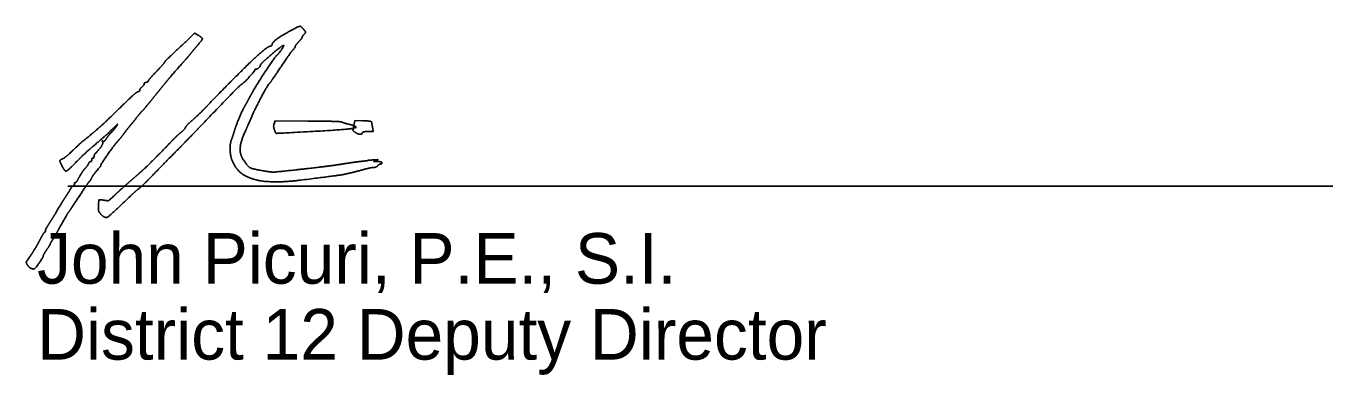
# Model space of a CAD drawing. Extents: x 0 to 34, y 0 to 22.
# Drawn here: x 25.965 to 29.58, y 2.758 to 3.723 of the extents above; entities that cross this region are included whole.
import ezdxf

# ---------------------------------------------------------------- set-up
doc = ezdxf.new("R2010")
doc.units = 0
doc.layers.add('SH_Data', color=7, linetype='Continuous')
doc.layers.add('SH_Text', color=7, linetype='Continuous')

msp = doc.modelspace()

# ---------------------------------------------------------------- linework, layer by layer
at = {"layer": 'SH_Data'}
msp.add_line((26.0803, 3.2806), (29.5803, 3.2806), dxfattribs=at)
at = {"layer": 'SH_Text'}
for p, q in [((26.6518, 3.4365), (26.6518, 3.4365)), ((26.8747, 3.4296), (26.8747, 3.4296)), ((26.1704, 3.204), (26.1704, 3.204)), ((25.9794, 3.0525), (25.9794, 3.0525))]:
    msp.add_line(p, q, dxfattribs=at)
for points in [[(26.4203, 3.693), (26.4311, 3.7036), (26.4407, 3.6979)], [(26.2143, 3.4456), (26.2176, 3.452), (26.2113, 3.4456)], [(26.7445, 3.4603), (26.6539, 3.4608), (26.6512, 3.4529)], [(26.8963, 3.4611), (26.8745, 3.4616), (26.8716, 3.4479)], [(26.91, 3.4312), (26.9248, 3.4312), (26.9231, 3.4442)]]:
    msp.add_lwpolyline(points, dxfattribs=at)
for points in [[(26.3787, 3.6538), (26.3956, 3.6695), (26.4143, 3.6871), (26.4203, 3.693)], [(26.4407, 3.6979), (26.4523, 3.6911), (26.4529, 3.685), (26.4431, 3.6743)], [(26.6456, 3.6725), (26.6456, 3.6777), (26.6716, 3.6968), (26.6977, 3.7108)], [(26.6977, 3.7108), (26.7203, 3.7229), (26.7254, 3.7229), (26.7351, 3.7113)], [(26.7288, 3.6923), (26.7288, 3.6911), (26.7245, 3.6854), (26.7192, 3.6798)], [(26.734, 3.7005), (26.7312, 3.6973), (26.7288, 3.6936), (26.7288, 3.6923)], [(26.7351, 3.7113), (26.7386, 3.7071), (26.7384, 3.7053), (26.734, 3.7005)], [(26.348, 3.6231), (26.348, 3.6242), (26.3618, 3.638), (26.3787, 3.6538)], [(26.4431, 3.6743), (26.4392, 3.67), (26.4302, 3.6592), (26.4231, 3.6505)], [(26.4663, 3.5026), (26.5366, 3.5762), (26.6286, 3.6644), (26.6374, 3.6666)], [(26.6776, 3.6693), (26.6776, 3.6716), (26.6526, 3.6522), (26.6291, 3.6318)], [(26.6374, 3.6666), (26.6419, 3.6677), (26.6456, 3.6704), (26.6456, 3.6725)], [(26.6602, 3.644), (26.6648, 3.648), (26.6776, 3.6667), (26.6776, 3.6693)], [(26.7056, 3.6599), (26.6975, 3.6508), (26.6943, 3.6464), (26.6679, 3.6072)], [(26.7096, 3.6669), (26.7096, 3.6655), (26.7078, 3.6623), (26.7056, 3.6599)], [(26.7192, 3.6798), (26.7139, 3.6742), (26.7096, 3.6684), (26.7096, 3.6669)], [(26.3256, 3.5976), (26.3379, 3.6105), (26.348, 3.622), (26.348, 3.6231)], [(26.4056, 3.6295), (26.3943, 3.6174), (26.3634, 3.582), (26.3527, 3.5688)], [(26.4231, 3.6505), (26.4161, 3.6418), (26.4082, 3.6323), (26.4056, 3.6295)], [(26.5863, 3.5314), (26.5982, 3.5538), (26.6536, 3.6382), (26.6602, 3.644)], [(26.6136, 3.6157), (26.6136, 3.6119), (26.605, 3.604), (26.601, 3.604)], [(26.6291, 3.6318), (26.6206, 3.6244), (26.6137, 3.6172), (26.6136, 3.6157)], [(26.3032, 3.5717), (26.3032, 3.573), (26.3133, 3.5847), (26.3256, 3.5976)], [(26.5975, 3.6016), (26.5974, 3.5987), (26.5643, 3.5624), (26.5618, 3.5624)], [(26.601, 3.604), (26.5991, 3.604), (26.5976, 3.6029), (26.5975, 3.6016)], [(26.6679, 3.6072), (26.6531, 3.5852), (26.6402, 3.5665), (26.6393, 3.5656)], [(26.2748, 3.5417), (26.2784, 3.5428), (26.2805, 3.5446), (26.2795, 3.5455)], [(26.2795, 3.5455), (26.2785, 3.5465), (26.2812, 3.5506), (26.2854, 3.5545)], [(26.2854, 3.5545), (26.2897, 3.5585), (26.2925, 3.5624), (26.2916, 3.5633)], [(26.2916, 3.5633), (26.2907, 3.5642), (26.2929, 3.5659), (26.2966, 3.5671)], [(26.2966, 3.5671), (26.3002, 3.5683), (26.3032, 3.5703), (26.3032, 3.5717)], [(26.3527, 3.5688), (26.3463, 3.5609), (26.3363, 3.5486), (26.3305, 3.5416)], [(26.5618, 3.5624), (26.5598, 3.5624), (26.5291, 3.5312), (26.4594, 3.4585)], [(26.6393, 3.5656), (26.6324, 3.5591), (26.5929, 3.4832), (26.58, 3.452)], [(26.1458, 3.4241), (26.1631, 3.4383), (26.1971, 3.4698), (26.2383, 3.5102)], [(26.2383, 3.5102), (26.2549, 3.5264), (26.2713, 3.5406), (26.2748, 3.5417)], [(26.3046, 3.5096), (26.2961, 3.499), (26.2875, 3.4889), (26.2855, 3.4872)], [(26.3305, 3.5416), (26.3248, 3.5345), (26.3131, 3.5201), (26.3046, 3.5096)], [(26.5717, 3.5048), (26.5734, 3.5074), (26.5799, 3.5194), (26.5863, 3.5314)], [(26.2855, 3.4872), (26.2835, 3.4854), (26.2762, 3.4768), (26.2693, 3.468)], [(26.4255, 3.4632), (26.4364, 3.4729), (26.4548, 3.4906), (26.4663, 3.5026)], [(26.5416, 3.4344), (26.5465, 3.4507), (26.565, 3.4938), (26.5717, 3.5048)], [(26.2113, 3.4456), (26.1995, 3.4336), (26.1769, 3.4132), (26.1528, 3.3928)], [(26.2016, 3.4296), (26.2067, 3.4349), (26.2124, 3.4421), (26.2143, 3.4456)], [(26.255, 3.4504), (26.2541, 3.4495), (26.2465, 3.4399), (26.2382, 3.429)], [(26.2693, 3.468), (26.2624, 3.4592), (26.256, 3.4513), (26.255, 3.4504)], [(26.4594, 3.4585), (26.4342, 3.4322), (26.3985, 3.3954), (26.38, 3.3767)], [(26.3939, 3.4295), (26.4003, 3.4348), (26.4056, 3.4406), (26.4056, 3.4424)], [(26.4056, 3.4424), (26.4056, 3.4442), (26.4146, 3.4536), (26.4255, 3.4632)], [(26.58, 3.452), (26.5771, 3.4449), (26.5734, 3.4363), (26.5718, 3.4328)], [(26.6512, 3.4529), (26.6497, 3.4483), (26.6499, 3.4414), (26.6518, 3.4365)], [(26.6518, 3.4365), (26.6557, 3.4263), (26.6587, 3.4262), (26.7512, 3.4312)], [(26.8388, 3.4575), (26.8368, 3.4588), (26.7944, 3.4601), (26.7445, 3.4603)], [(26.7512, 3.4312), (26.8528, 3.4366), (26.8897, 3.444), (26.8559, 3.452)], [(26.8559, 3.452), (26.8485, 3.4537), (26.8408, 3.4562), (26.8388, 3.4575)], [(26.8716, 3.4479), (26.8691, 3.4361), (26.8695, 3.4335), (26.8747, 3.4296)], [(26.9197, 3.4589), (26.9188, 3.4598), (26.9083, 3.4608), (26.8963, 3.4611)], [(26.9231, 3.4442), (26.9221, 3.4514), (26.9206, 3.458), (26.9197, 3.4589)], [(26.0927, 3.3776), (26.114, 3.3979), (26.1197, 3.4028), (26.1458, 3.4241)], [(26.1569, 3.3709), (26.1685, 3.3829), (26.1787, 3.3993), (26.1766, 3.4027)], [(26.2189, 3.405), (26.2122, 3.3982), (26.172, 3.3419), (26.172, 3.3392)], [(26.1766, 3.4027), (26.1752, 3.405), (26.1756, 3.4057), (26.1776, 3.4045)], [(26.1776, 3.4045), (26.1794, 3.4034), (26.1834, 3.4064), (26.1866, 3.4112)], [(26.1866, 3.4112), (26.1897, 3.416), (26.1964, 3.4243), (26.2016, 3.4296)], [(26.2382, 3.429), (26.2299, 3.4181), (26.2212, 3.4073), (26.2189, 3.405)], [(26.28, 3.3176), (26.2927, 3.3287), (26.3383, 3.3739), (26.3643, 3.4012)], [(26.3643, 3.4012), (26.3742, 3.4115), (26.3875, 3.4243), (26.3939, 3.4295)], [(26.5351, 3.3508), (26.5299, 3.3628), (26.5288, 3.3981), (26.5333, 3.4094)], [(26.5333, 3.4094), (26.535, 3.4135), (26.5387, 3.4247), (26.5416, 3.4344)], [(26.5718, 3.4328), (26.5589, 3.4053), (26.5557, 3.3692), (26.5648, 3.3551)], [(26.8747, 3.4296), (26.8817, 3.4243), (26.8952, 3.4232), (26.8952, 3.428)], [(26.8952, 3.428), (26.8952, 3.4297), (26.9019, 3.4312), (26.91, 3.4312)], [(26.0658, 3.3558), (26.069, 3.3568), (26.0811, 3.3666), (26.0927, 3.3776)], [(26.1528, 3.3928), (26.1396, 3.3816), (26.1207, 3.3642), (26.1109, 3.3543)], [(26.1528, 3.3621), (26.1528, 3.3647), (26.1546, 3.3686), (26.1569, 3.3709)], [(26.38, 3.3767), (26.3615, 3.358), (26.3331, 3.3289), (26.3168, 3.3121)], [(26.0649, 3.335), (26.0584, 3.3475), (26.0587, 3.3535), (26.0658, 3.3558)], [(26.1109, 3.3543), (26.0798, 3.3229), (26.0727, 3.3199), (26.0649, 3.335)], [(26.1122, 3.3058), (26.1168, 3.3142), (26.124, 3.3249), (26.1282, 3.3294)], [(26.1282, 3.3294), (26.1324, 3.334), (26.1367, 3.34), (26.1378, 3.3428)], [(26.1378, 3.3428), (26.1389, 3.3457), (26.1413, 3.348), (26.1431, 3.348)], [(26.1431, 3.348), (26.1449, 3.348), (26.1464, 3.3501), (26.1464, 3.3528)], [(26.1464, 3.3528), (26.1464, 3.3554), (26.1478, 3.3576), (26.1496, 3.3576)], [(26.1496, 3.3576), (26.1514, 3.3576), (26.1528, 3.3596), (26.1528, 3.3621)], [(26.172, 3.3392), (26.172, 3.3371), (26.1686, 3.3326), (26.1533, 3.3142)], [(26.5974, 3.2987), (26.5717, 3.3063), (26.5447, 3.3289), (26.5351, 3.3508)], [(26.5648, 3.3551), (26.5776, 3.3351), (26.5908, 3.3277), (26.6234, 3.3222)], [(26.7112, 3.3253), (26.7672, 3.3314), (26.8172, 3.3378), (26.8488, 3.3428)], [(26.8488, 3.3428), (26.8616, 3.3448), (26.8917, 3.3488), (26.9016, 3.3498)], [(26.9262, 3.3319), (26.9223, 3.3319), (26.9084, 3.3289), (26.8952, 3.3253)], [(26.9016, 3.3498), (26.906, 3.3503), (26.9096, 3.3509), (26.9096, 3.3512)], [(26.9096, 3.3512), (26.9096, 3.3515), (26.9168, 3.3522), (26.9256, 3.3529)], [(26.9256, 3.3529), (26.9373, 3.3537), (26.9395, 3.3533), (26.9336, 3.3513)], [(26.9379, 3.3368), (26.9353, 3.3341), (26.93, 3.3319), (26.9262, 3.3319)], [(26.9336, 3.3513), (26.9264, 3.3489), (26.9267, 3.3486), (26.9376, 3.3483)], [(26.9376, 3.3483), (26.9442, 3.3481), (26.9496, 3.3465), (26.9496, 3.3448)], [(26.9462, 3.3416), (26.9443, 3.3416), (26.9406, 3.3394), (26.9379, 3.3368)], [(26.9496, 3.3448), (26.9496, 3.343), (26.9481, 3.3416), (26.9462, 3.3416)], [(26.0984, 3.2856), (26.0984, 3.2882), (26.0996, 3.2904), (26.1011, 3.2904)], [(26.1011, 3.2904), (26.1026, 3.2904), (26.1075, 3.2973), (26.1122, 3.3058)], [(26.1401, 3.2936), (26.1389, 3.2927), (26.1262, 3.274), (26.1117, 3.252)], [(26.1463, 3.303), (26.1441, 3.2987), (26.1413, 3.2945), (26.1401, 3.2936)], [(26.1533, 3.3142), (26.1517, 3.3123), (26.1486, 3.3073), (26.1463, 3.303)], [(26.212, 3.2572), (26.2226, 3.2671), (26.2397, 3.2825), (26.2501, 3.2915)], [(26.2501, 3.2915), (26.2605, 3.3006), (26.274, 3.3123), (26.28, 3.3176)], [(26.3168, 3.3121), (26.3006, 3.2953), (26.2829, 3.2781), (26.2775, 3.274)], [(26.724, 3.2968), (26.6833, 3.2917), (26.6176, 3.2927), (26.5974, 3.2987)], [(26.6234, 3.3222), (26.6441, 3.3188), (26.6555, 3.3192), (26.7112, 3.3253)], [(26.8952, 3.3253), (26.8575, 3.315), (26.8183, 3.3085), (26.724, 3.2968)], [(26.0757, 3.2532), (26.0803, 3.2601), (26.0859, 3.2691), (26.0882, 3.2732)], [(26.0882, 3.2732), (26.0905, 3.2774), (26.0937, 3.2808), (26.0954, 3.2808)], [(26.0954, 3.2808), (26.097, 3.2808), (26.0984, 3.2829), (26.0984, 3.2856)], [(26.1812, 3.2412), (26.1919, 3.2395), (26.1943, 3.2407), (26.212, 3.2572)], [(26.2775, 3.274), (26.2721, 3.2698), (26.2573, 3.2564), (26.2446, 3.2442)], [(26.0438, 3.2011), (26.0608, 3.2298), (26.0685, 3.2423), (26.0757, 3.2532)], [(26.1117, 3.252), (26.0973, 3.23), (26.0842, 3.2104), (26.0828, 3.2086)], [(26.1704, 3.204), (26.1665, 3.2083), (26.1647, 3.2148), (26.1651, 3.2235)], [(26.1651, 3.2235), (26.1658, 3.2412), (26.1677, 3.2434), (26.1812, 3.2412)], [(26.2446, 3.2442), (26.197, 3.1985), (26.1825, 3.1906), (26.1704, 3.204)], [(26.0288, 3.1771), (26.0345, 3.1861), (26.0413, 3.1968), (26.0438, 3.2011)], [(26.0828, 3.2086), (26.0803, 3.2054), (26.076, 3.198), (26.0547, 3.16)], [(26.0034, 3.132), (26.0088, 3.1425), (26.0145, 3.1517), (26.0159, 3.1522)], [(26.0159, 3.1522), (26.0173, 3.1528), (26.0184, 3.155), (26.0184, 3.1571)], [(26.0184, 3.1571), (26.0184, 3.1592), (26.0231, 3.1682), (26.0288, 3.1771)], [(26.0547, 3.16), (26.05, 3.1516), (26.0428, 3.1394), (26.0387, 3.1328)], [(25.979, 3.0907), (25.9869, 3.1028), (25.9979, 3.1214), (26.0034, 3.132)], [(26.0312, 3.1194), (26.0312, 3.1186), (26.0269, 3.1115), (26.0216, 3.1037)], [(26.0387, 3.1328), (26.0346, 3.1263), (26.0312, 3.1202), (26.0312, 3.1194)], [(25.9693, 3.0613), (25.9647, 3.0682), (25.9653, 3.0699), (25.979, 3.0907)], [(26.012, 3.0869), (26.012, 3.0833), (25.9889, 3.0503), (25.9867, 3.0507)], [(26.0216, 3.1037), (26.0163, 3.0958), (26.012, 3.0883), (26.012, 3.0869)], [(25.9794, 3.0525), (25.9765, 3.0533), (25.9719, 3.0573), (25.9693, 3.0613)], [(25.9867, 3.0507), (25.9856, 3.0509), (25.9824, 3.0518), (25.9794, 3.0525)]]:
    msp.add_open_spline(points, degree=2, dxfattribs=at)

# ---------------------------------------------------------------- texts
for s, p in [('John Picuri, P.E., S.I.', (25.9954, 3.0104)), ('District 12 Deputy Director              ', (25.9954, 2.8004))]:
    msp.add_text(s, height=0.14, dxfattribs=at).set_placement(p)

doc.saveas('drawing.dxf')
